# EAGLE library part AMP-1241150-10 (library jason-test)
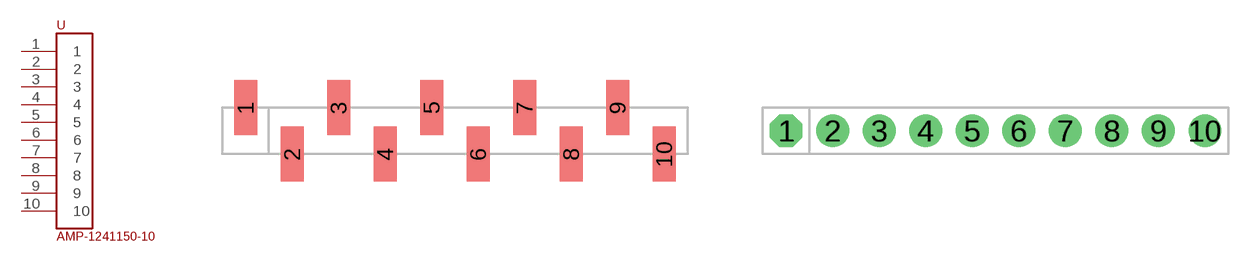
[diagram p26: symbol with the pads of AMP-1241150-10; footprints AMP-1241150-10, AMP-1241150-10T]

Designator prefix -

## AMP-1241150-10SMD  [AMP-1241150-10]
1  1
2  2
3  3
4  4
5  5
6  6
7  7
8  8
9  9
10  10

## AMP-1241150-10PTH  [AMP-1241150-10T]
Pads as for AMP-1241150-10

## Footprint AMP-1241150-10 (pad centres in mm)
smd 1.27 x 3: 1 -11.43,1.27; 2 -8.89,-1.27; 3 -6.35,1.27; 4 -3.81,-1.27; 5 -1.27,1.27; 6 1.27,-1.27; 7 3.81,1.27; 8 6.35,-1.27; 9 8.89,1.27; 10 11.43,-1.27

## Footprint AMP-1241150-10T (pad centres in mm)
drill 1 pad 1.778 octagon: 1 -11.43,0
drill 1 pad 1.778 round: 2 -8.89,0; 3 -6.35,0; 4 -3.81,0; 5 -1.27,0; 6 1.27,0; 7 3.81,0; 8 6.35,0; 9 8.89,0; 10 11.43,0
